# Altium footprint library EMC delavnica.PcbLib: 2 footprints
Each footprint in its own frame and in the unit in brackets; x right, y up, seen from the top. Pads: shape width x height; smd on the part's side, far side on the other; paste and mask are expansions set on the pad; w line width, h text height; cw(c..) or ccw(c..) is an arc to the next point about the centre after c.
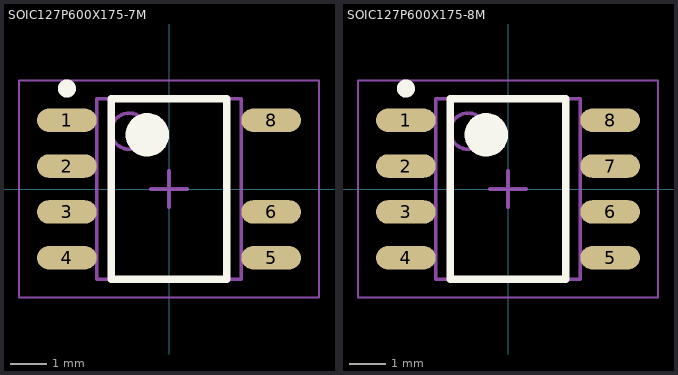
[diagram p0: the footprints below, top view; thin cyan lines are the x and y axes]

## SOIC127P600X175-7M [mm] "SOIC, 8-Leads, Body 4.90x3.90mm, Pitch 1.27mm, IPC Low Density"
height 1.75
pads (7):
  oval 1.65x0.65 smd: 1(-2.825,1.905) 2(-2.825,0.635) 3(-2.825,-0.635) 4(-2.825,-1.905) 5(2.825,-1.905) 6(2.825,-0.635) 8(2.825,1.905)
Top Overlay:
  circle w0.25: c-2.825,2.78 r0.125
  circle w0.6: c-0.6,1.5 r0.3
  lines w0.2: -1.6,-2.5 -1.6,2.5 1.6,2.5 1.6,-2.5 -1.6,-2.5
Mechanical 13:
  circle w0.1: c-1.1,1.6 r0.5
  lines w0.1: -2,-2.5 -2,2.5 2,2.5 2,-2.5 -2,-2.5
Mechanical 15:
  lines w0.05: -4.15,-3 -4.15,3 4.15,3 4.15,-3 -4.15,-3
  lines w0.1: -0.5,0 0.5,0 ; 0,-0.5 0,0.5
3D body "SOIC127P600X175-8M.step": height 1.75, standoff 0, extent -3,-2.5 3,2.5

## SOIC127P600X175-8M [mm] "SOIC, 8-Leads, Body 4.90x3.90mm, Pitch 1.27mm, IPC Low Density"
height 1.75
pads (8):
  oval 1.65x0.65 smd: 1(-2.825,1.905) 2(-2.825,0.635) 3(-2.825,-0.635) 4(-2.825,-1.905) 5(2.825,-1.905) 6(2.825,-0.635) 7(2.825,0.635) 8(2.825,1.905)
Top Overlay:
  circle w0.25: c-2.825,2.78 r0.125
  circle w0.6: c-0.6,1.5 r0.3
  lines w0.2: -1.6,-2.5 -1.6,2.5 1.6,2.5 1.6,-2.5 -1.6,-2.5
Mechanical 13:
  circle w0.1: c-1.1,1.6 r0.5
  lines w0.1: -2,-2.5 -2,2.5 2,2.5 2,-2.5 -2,-2.5
Mechanical 15:
  lines w0.05: -4.15,-3 -4.15,3 4.15,3 4.15,-3 -4.15,-3
  lines w0.1: -0.5,0 0.5,0 ; 0,-0.5 0,0.5
3D body "SOIC127P600X175-8M.step": height 1.75, standoff 0, extent -3,-2.5 3,2.5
